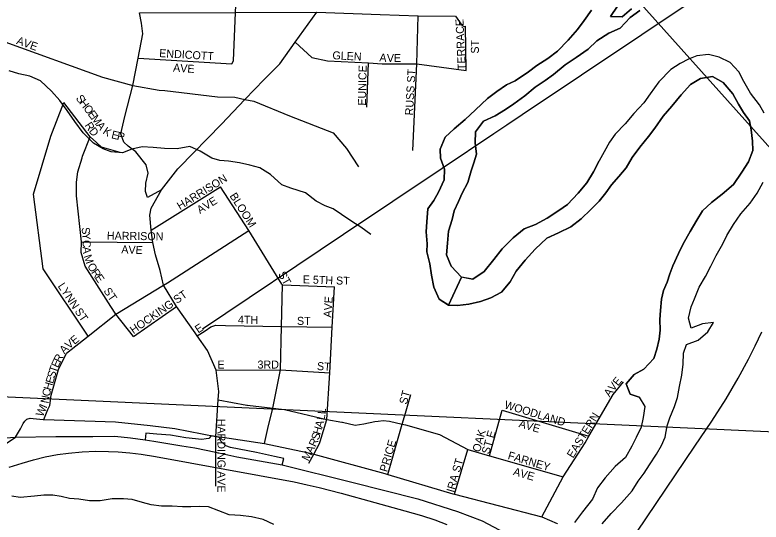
# Model space of a CAD drawing. Extents: x 1624196 to 2029251, y 146837 to 440034.
# Drawn here: x 1855581 to 1860244, y 275807 to 278973 of the extents above; entities that cross this region are included whole.
import ezdxf

# ---------------------------------------------------------------- set-up
doc = ezdxf.new("R2010")
doc.units = 0
for name, color, linetype in [('GM_P_State_Alignment', 7, 'Continuous'), ('GM_X_City_Street', 7, 'Continuous'), ('GM_X_City_Street_Text', 7, 'Continuous'), ('GM_X_Interchange_Ramps', 7, 'Continuous'), ('GM_X_Major_River', 7, 'Continuous'), ('GM_X_Minor_River', 7, 'Continuous'), ('GM_X_Rail_Line', 7, 'Continuous'), ('GM_X_Section', 7, 'Continuous'), ('GM_X_State_Route', 7, 'Continuous'), ('GM_X_US_Route', 7, 'Continuous')]:
    doc.layers.add(name, color=color, linetype=linetype)

msp = doc.modelspace()

# ---------------------------------------------------------------- linework, layer by layer
at = {"layer": 'GM_P_State_Alignment'}
msp.add_lwpolyline([(1861511.5, 276861.7), (1860431.7, 277996.1), (1859184.2, 279387.8), (1858872.6, 279744.1), (1858597.3, 280059.1), (1857442.1, 281556), (1857427.3, 281575.2), (1856929.1, 281940.1)], dxfattribs=at)
at = {"layer": 'GM_X_City_Street'}
for points in [[(1856947.1, 278686.4), (1856960, 278987.7), (1856972.7, 279283.3), (1856984.8, 279567.1)], [(1856496.6, 277882), (1856409.1, 277834), (1856397.6, 277871.4), (1856398.6, 277922.3), (1856413.5, 277986.2), (1856401.5, 278037.1), (1856335.8, 278117.6), (1856289.3, 278154.3), (1856261.8, 278178.9), (1856241.9, 278231.8), (1856267.8, 278338.6), (1856317.2, 278532.3), (1856350.2, 278702.4), (1856379.8, 278855.1), (1856372.2, 278921.9), (1856359.9, 278985.6)], [(1856359.9, 278985.6), (1856960, 278987.7), (1857468.3, 278989.5), (1857862.5, 278976.5), (1858101, 278967.5), (1858333, 278965.5), (1858374.4, 278910.1), (1858388.3, 278901.9), (1858396.4, 278903.8)], [(1858067.7, 278127), (1858093, 278667), (1858101, 278967.5)], [(1858401.6, 278626.9), (1858396.4, 278903.8)], [(1855518.1, 278804.9), (1856127.6, 278584.2), (1856317.2, 278532.3), (1856482.9, 278504.3), (1856517, 278500.3)], [(1857331.6, 278802.8), (1857436.4, 278707), (1857534.1, 278686), (1857789.6, 278674), (1857875.4, 278668), (1858093, 278667), (1858401.6, 278626.9)], [(1856350.2, 278702.4), (1856936.9, 278668.4), (1856947.1, 278686.4)], [(1857779.9, 278396.8), (1857789.6, 278674)], [(1856517, 278500.3), (1856846.6, 278461.4), (1856955.4, 278459.4), (1857018.2, 278445.4), (1857073.1, 278434.4), (1857296.6, 278343.6), (1857569.1, 278237.8), (1857653, 278139.3), (1857728, 278024.2)], [(1856038.1, 276968.4), (1855757.3, 277388.9), (1855696, 277855), (1855805.9, 278216.9), (1855886.2, 278426.7)], [(1856090.7, 278175.8), (1856090.1, 278176.2), (1856050.4, 278212.3), (1855886.2, 278426.7)], [(1856000.1, 278081), (1856002.9, 278090.8), (1856050.4, 278212.3)], [(1856237.4, 278114.8), (1856121.9, 278147.4), (1856090.7, 278175.8)], [(1856181, 277153.3), (1856019.3, 277404), (1855994.5, 277489.5), (1855996.9, 277556.3), (1855964.9, 277843.9), (1855964.9, 277928.6), (1855974.7, 277993.5), (1856000.1, 278081)], [(1856432, 277630.3), (1856866.1, 277900.3)], [(1857249.2, 277292.4), (1857042.4, 277628.1), (1856866.1, 277900.3)], [(1856533.3, 277300.8), (1857042.4, 277628.1)], [(1855996.9, 277556.3), (1856442.4, 277552.2)], [(1855760.6, 276447.4), (1855786.5, 276510.8), (1855799, 276535.7), (1855808, 276599.1), (1855854, 276759.4), (1855902.2, 276861.9), (1856038.1, 276968.4), (1856212.2, 277105), (1856509.9, 277285.7), (1856533.3, 277300.8)], [(1857161.9, 276391.5), (1857192.4, 276517.5), (1857240.7, 276757.7), (1857247.4, 277027.8), (1857251.8, 277288.3), (1857249.2, 277292.4)], [(1857251.8, 277288.3), (1857577.7, 277274.8)], [(1857487.7, 276310.6), (1857529, 276447.1), (1857548.3, 276738.4), (1857564.2, 277024), (1857577.7, 277274.8)], [(1856321.7, 276966), (1856212.2, 277105), (1856181, 277153.3)], [(1856321.7, 276966), (1856590.5, 277153.7)], [(1856719.8, 276969.3), (1856769.4, 277000.6), (1856804.9, 277025.4), (1856837, 277036.2), (1856897.3, 277035)], [(1856897.3, 277035), (1857247.4, 277027.8), (1857564.2, 277024)], [(1856837.6, 276755.8), (1857240.7, 276757.7), (1857548.3, 276738.4)], [(1858873.3, 275840.3), (1859006.8, 276089.1), (1859143.3, 276302.3), (1859167.5, 276344), (1859318.7, 276603.4), (1859383.6, 276682.9)], [(1858021, 276487.7), (1858021, 276487.7), (1858054.1, 276602.6)], [(1856850.1, 276569.6), (1857029.5, 276536.8), (1857033.2, 276536.3)], [(1857033.2, 276536.3), (1857192.4, 276517.5), (1857264.8, 276509.8), (1857529, 276447.1), (1857623.5, 276431.6), (1857627.9, 276430.6)], [(1857910.6, 276104.9), (1858001.2, 276419.1), (1858021, 276487.7)], [(1858546.2, 276220.8), (1858626.3, 276506.3)], [(1858626.3, 276506.3), (1859167.5, 276344)], [(1857627.9, 276430.6), (1857706, 276412.3), (1857761.9, 276420.1), (1857829.4, 276435.5), (1857850.6, 276437.4), (1857881.5, 276441.3), (1857922, 276437.4), (1858001.2, 276419.1), (1858022.3, 276414.3), (1858234.5, 276354.5), (1858411.1, 276259.4), (1858546.2, 276220.8), (1859006.8, 276089.1)], [(1857139.3, 276298.4), (1857161.9, 276391.5)], [(1856836.2, 276134.6), (1856836.2, 276134.7), (1856836.3, 276242.6), (1856836.4, 276342.3)], [(1856836.4, 276342.3), (1856877.2, 276336.8), (1857139.3, 276298.4), (1857407.3, 276242.1), (1857448.5, 276231), (1857892.6, 276110.2), (1857910.6, 276104.9), (1858317.8, 275984), (1858327.1, 275981.6), (1858873.3, 275840.3), (1858970.2, 275797.4), (1858972.2, 275796.5)], [(1857418.3, 276174), (1857448.5, 276231), (1857483.7, 276297.5), (1857487.7, 276310.6)], [(1858327.1, 275981.6), (1858411.1, 276259.4)], [(1856835.7, 276030.8), (1856836.2, 276134.6)]]:
    msp.add_lwpolyline(points, dxfattribs=at)
at = {"layer": 'GM_X_Interchange_Ramps'}
for points in [[(1856836.4, 276342.3), (1856806.1, 276344.5), (1856791.7, 276327.8), (1856775, 276325.7), (1856747.8, 276323.6), (1856647.7, 276334), (1856553.7, 276348.7), (1856468.2, 276355.9), (1856399.1, 276363.1), (1856394.3, 276320.3)], [(1857251.5, 276165.4), (1857260.6, 276203.8), (1857203.1, 276217.1), (1857089.5, 276242.2), (1856928.7, 276273.2), (1856897.7, 276283.5), (1856866.7, 276311.6), (1856858.6, 276334.9), (1856836.4, 276342.3)]]:
    msp.add_lwpolyline(points, dxfattribs=at)
at = {"layer": 'GM_X_Major_River'}
for p, q in [((1858370.4, 277336.8), (1858290.1, 277161.8)), ((1858290.1, 277161.8), (1858370.4, 277336.8))]:
    msp.add_line(p, q, dxfattribs=at)
for points in [[(1859433.2, 279010.7), (1859375.4, 278960.5), (1859303.4, 278964.3), (1859347.2, 279028.5)], [(1859347.2, 279028.5), (1859303.4, 278964.3), (1859375.4, 278960.5), (1859433.2, 279010.7)], [(1859183.4, 279002.1), (1859137.5, 278937.9), (1859095.7, 278881.7), (1859037.9, 278815.5), (1858972, 278747.2), (1858910.2, 278701), (1858842.3, 278656.8), (1858790.4, 278618.6), (1858706.6, 278562.3), (1858652.7, 278536.2), (1858592.8, 278496), (1858532.9, 278451.8), (1858459.1, 278381.5), (1858395.3, 278321.3), (1858325.5, 278261), (1858269.6, 278210.8), (1858237.8, 278134.6), (1858239.9, 278078.5), (1858266.1, 278010.5), (1858262.2, 277944.4), (1858228.4, 277866.2), (1858198.6, 277814), (1858160.7, 277761.9), (1858154.9, 277681.8), (1858151, 277619.6), (1858157.2, 277543.5), (1858155.3, 277493.5), (1858173.5, 277419.4), (1858183.6, 277349.3), (1858197.8, 277273.2), (1858232, 277199.2), (1858290.1, 277161.8)], [(1859480.7, 276587.2), (1859424.7, 276605.1), (1859400.6, 276669.1), (1859450.4, 276729.3), (1859510.3, 276761.5), (1859574.1, 276827.8), (1859592, 276885.9), (1859605.9, 276948), (1859613.7, 277006.1), (1859611.6, 277072.2), (1859615.4, 277128.3), (1859621.3, 277198.5), (1859633.1, 277252.6), (1859657, 277304.7), (1859672.9, 277356.8), (1859692.8, 277406.9), (1859726.6, 277483.1), (1859756.4, 277543.3), (1859800.2, 277621.5), (1859842, 277691.7), (1859877.9, 277749.9), (1859933.7, 277802.1), (1859999.6, 277854.3), (1860071.4, 277914.6), (1860123.2, 277990.8), (1860165, 278055), (1860192.9, 278127.2), (1860190.7, 278185.2), (1860182.6, 278255.3), (1860170.5, 278311.4), (1860134.3, 278363.4), (1860102.2, 278415.4), (1860066.1, 278481.4), (1860006, 278551.4), (1859939.9, 278589.3), (1859864, 278577.1), (1859802.1, 278538.9), (1859744.3, 278474.6), (1859686.5, 278404.4), (1859630.7, 278340.2), (1859578.9, 278265.9), (1859541, 278213.8), (1859485.2, 278147.5), (1859437.3, 278083.3), (1859399.5, 278019.1), (1859353.7, 277965), (1859307.8, 277912.8), (1859273.9, 277862.6), (1859232.1, 277810.5), (1859180.2, 277758.3), (1859118.4, 277700), (1859054.5, 277649.8), (1858978.6, 277613.6), (1858904.8, 277579.3), (1858831, 277511.1), (1858769.1, 277442.8), (1858713.3, 277372.6), (1858675.5, 277306.4), (1858621.7, 277242.2), (1858553.8, 277208), (1858489.9, 277183.8), (1858417.9, 277167.6), (1858346, 277159.4), (1858294, 277159.3), (1858232, 277199.2), (1858197.8, 277273.2), (1858183.6, 277349.3), (1858173.5, 277419.4), (1858155.3, 277493.5), (1858157.2, 277543.5), (1858151, 277619.6), (1858154.9, 277681.8), (1858160.7, 277761.9), (1858198.6, 277814), (1858228.4, 277866.2), (1858262.2, 277944.4), (1858266.1, 278010.5), (1858239.9, 278078.5), (1858237.8, 278134.6), (1858269.6, 278210.8), (1858325.5, 278261), (1858395.3, 278321.3), (1858459.1, 278381.5), (1858532.9, 278451.8), (1858592.8, 278496), (1858652.7, 278536.2), (1858706.6, 278562.3), (1858790.4, 278618.6), (1858842.3, 278656.8), (1858910.2, 278701), (1858972, 278747.2), (1859037.9, 278815.5), (1859095.7, 278881.7), (1859137.5, 278937.9), (1859183.4, 279002.1)], [(1858370.4, 277336.8), (1858307.5, 277405.7), (1858277.3, 277475.7), (1858283.1, 277547.8), (1858291, 277624), (1858312.8, 277696.1), (1858326.6, 277750.3), (1858352.5, 277808.4), (1858376.4, 277860.5), (1858410.2, 277926.7), (1858432, 277998.9), (1858447.9, 278049), (1858465.8, 278103.1), (1858457.6, 278175.2), (1858459.5, 278243.3), (1858509.3, 278309.5), (1858581.2, 278343.7), (1858647, 278381.9), (1858698.9, 278418.1), (1858766.8, 278468.3), (1858832.6, 278522.6), (1858894.5, 278564.8), (1858946.4, 278601), (1859020.2, 278661.2), (1859088.1, 278707.5), (1859163.9, 278759.7), (1859217.8, 278811.9), (1859291.6, 278860.2), (1859363.5, 278890.4), (1859425.3, 278956.6), (1859485.2, 279000.8)], [(1859485.2, 279000.8), (1859425.3, 278956.6), (1859363.5, 278890.4), (1859291.6, 278860.2), (1859217.8, 278811.9), (1859163.9, 278759.7), (1859088.1, 278707.5), (1859020.2, 278661.2), (1858946.4, 278601), (1858894.5, 278564.8), (1858832.6, 278522.6), (1858766.8, 278468.3), (1858698.9, 278418.1), (1858647, 278381.9), (1858581.2, 278343.7), (1858509.3, 278309.5), (1858459.5, 278243.3), (1858457.6, 278175.2), (1858465.8, 278103.1), (1858447.9, 278049), (1858432, 277998.9), (1858410.2, 277926.7), (1858376.4, 277860.5), (1858352.5, 277808.4), (1858326.6, 277750.3), (1858312.8, 277696.1), (1858291, 277624), (1858283.1, 277547.8), (1858277.3, 277475.7), (1858307.5, 277405.7), (1858369.6, 277337.7), (1858441.6, 277323.9), (1858513.4, 277372.1), (1858573.2, 277446.4), (1858625, 277512.6), (1858694.9, 277580.9), (1858762.7, 277637.1), (1858834.6, 277665.3), (1858906.5, 277703.5), (1858980.3, 277751.8), (1859034.2, 277790), (1859100, 277860.2), (1859153.8, 277924.4), (1859195.7, 277994.6), (1859231.5, 278062.8)], [(1860262.3, 278359.7), (1860234.2, 278411.7), (1860178.1, 278485.7), (1860135.9, 278557.7), (1860103.8, 278617.7), (1860049.7, 278675.6), (1859981.6, 278709.5), (1859915.6, 278725.4), (1859841.7, 278717.2), (1859789.8, 278697.1), (1859737.8, 278670.9), (1859680, 278632.7), (1859604.2, 278556.4), (1859550.4, 278480.2), (1859510.5, 278424), (1859448.7, 278357.8), (1859394.9, 278293.5), (1859331.1, 278229.3), (1859297.2, 278179.2), (1859263.3, 278119), (1859231.5, 278062.8)], [(1858290.1, 277161.8), (1858346, 277159.4), (1858417.9, 277167.6), (1858489.9, 277183.8), (1858553.8, 277208), (1858621.7, 277242.2), (1858675.5, 277306.4), (1858713.3, 277372.6), (1858769.1, 277442.8), (1858831, 277511.1), (1858904.8, 277579.3), (1858978.6, 277613.6), (1859054.5, 277649.8), (1859118.4, 277700), (1859180.2, 277758.3), (1859232.1, 277810.5), (1859273.9, 277862.6), (1859307.8, 277912.8), (1859353.7, 277965), (1859399.5, 278019.1), (1859437.3, 278083.3), (1859485.2, 278147.5), (1859541, 278213.8), (1859578.9, 278265.9), (1859630.7, 278340.2), (1859686.5, 278404.4), (1859744.3, 278474.6), (1859802.1, 278538.9), (1859864, 278577.1), (1859939.9, 278589.3), (1860006, 278551.4), (1860066.1, 278481.4), (1860102.2, 278415.4), (1860134.3, 278363.4), (1860170.5, 278311.4), (1860182.6, 278255.3), (1860190.7, 278185.2), (1860192.9, 278127.2), (1860165, 278055), (1860123.2, 277990.8), (1860071.4, 277914.6), (1859999.6, 277854.3), (1859933.7, 277802.1), (1859877.9, 277749.9), (1859842, 277691.7), (1859800.2, 277621.5), (1859756.4, 277543.3), (1859726.6, 277483.1), (1859692.8, 277406.9), (1859672.9, 277356.8), (1859657, 277304.7), (1859633.1, 277252.6), (1859621.3, 277198.5), (1859615.4, 277128.3), (1859611.6, 277072.2), (1859613.7, 277006.1), (1859605.9, 276948), (1859592, 276885.9), (1859574.1, 276827.8), (1859510.3, 276761.5), (1859450.4, 276729.3), (1859400.6, 276669.1), (1859424.7, 276605.1), (1859480.7, 276587.2)], [(1859231.5, 278062.8), (1859195.7, 277994.6), (1859153.8, 277924.4), (1859100, 277860.2), (1859034.2, 277790), (1858980.3, 277751.8), (1858906.5, 277703.5), (1858834.6, 277665.3), (1858762.7, 277637.1), (1858694.9, 277580.9), (1858625, 277512.6), (1858573.2, 277446.4), (1858513.4, 277372.1), (1858441.6, 277323.9), (1858370.4, 277336.8)], [(1859250.7, 275795.5), (1859306.5, 275859.7), (1859370.3, 275928), (1859438.1, 276002.2), (1859475.9, 276062.4), (1859513.8, 276112.6), (1859545.7, 276164.7), (1859589.5, 276230.9), (1859621.4, 276285.1), (1859643.2, 276337.2), (1859657.1, 276407.4), (1859672.9, 276457.5), (1859702.8, 276529.6), (1859720.6, 276583.8), (1859734.5, 276653.9), (1859748.3, 276724), (1859756.1, 276792.2), (1859758, 276862.3), (1859777.8, 276916.4), (1859849.7, 276942.6), (1859911.6, 276994.8), (1859945.4, 277053), (1859877.5, 277044.8), (1859807.6, 277018.6), (1859789.5, 277080.7), (1859807.3, 277150.8), (1859827.2, 277200.9), (1859857, 277273.1), (1859896.8, 277339.3), (1859928.6, 277405.5), (1859962.5, 277471.6), (1860004.3, 277543.9), (1860030.2, 277596), (1860072, 277664.2), (1860117.8, 277730.4), (1860175.6, 277798.6), (1860219.5, 277860.8), (1860257.3, 277929)], [(1859480.7, 276587.2), (1859516.9, 276529.2), (1859507, 276459.1), (1859493.2, 276399), (1859463.3, 276334.8), (1859435.5, 276280.6), (1859395.6, 276210.5), (1859331.8, 276154.2), (1859270, 276084), (1859222.2, 276019.8), (1859190.3, 275949.6), (1859128.6, 275871.3), (1859076.7, 275805.1)], [(1857197.7, 275792.7), (1857131.7, 275822.6), (1857059.6, 275840.5), (1856989.7, 275848.3), (1856919.7, 275852.2), (1856855.7, 275878), (1856789.6, 275901.9), (1856733.7, 275903.8), (1856679.7, 275901.7), (1856627.7, 275901.5), (1856563.7, 275905.4), (1856495.8, 275907.2), (1856431.8, 275915.1), (1856377.8, 275929), (1856313.8, 275948.9), (1856259.8, 275952.8), (1856187.8, 275952.6), (1856113.9, 275940.4), (1856045.9, 275940.2), (1855979.9, 275950.1), (1855922, 275954), (1855870, 275965.9), (1855818, 275975.8), (1855762, 275975.6), (1855702, 275969.5), (1855614.1, 275961.3), (1855562.1, 275969.2)]]:
    msp.add_lwpolyline(points, dxfattribs=at)
at = {"layer": 'GM_X_Minor_River'}
msp.add_lwpolyline([(1857805.3, 277602.8), (1857743.2, 277648.8), (1857693.1, 277678.7), (1857621.1, 277726.6), (1857569, 277762.5), (1857519, 277780.4), (1857462.9, 277810.3), (1857396.9, 277862.2), (1857304.8, 277892.1), (1857248.8, 277912), (1857178.7, 277975.9), (1857110.6, 278017.8), (1857048.6, 278035.7), (1856984.6, 278049.6), (1856914.6, 278059.4), (1856860.7, 278065.3), (1856810.7, 278079.2), (1856738.6, 278123.1), (1856674.6, 278151), (1856594.6, 278136.8), (1856514.7, 278138.6), (1856444.7, 278146.5), (1856376.7, 278150.3), (1856310.8, 278134.1), (1856252.9, 278112), (1856182.9, 278117.8), (1856132.8, 278137.7), (1856070.8, 278171.6), (1856006.7, 278237.6), (1855954.5, 278307.5), (1855906.4, 278377.5), (1855860.3, 278439.5), (1855810.2, 278497.5), (1855740.1, 278561.4), (1855674, 278591.3), (1855606, 278605.2), (1855544, 278623.1)], dxfattribs=at)
at = {"layer": 'GM_X_Rail_Line'}
for points in [[(1861190.3, 279752.5), (1861042.6, 279708), (1860975.4, 279686.1), (1860887.1, 279656.4), (1860685.4, 279574.4), (1860439.3, 279471.2), (1860368.2, 279438.4), (1860307.2, 279406.3), (1860246.2, 279372), (1860189.2, 279332.9), (1860132.1, 279289.9), (1860066.5, 279239.1), (1859997.7, 279186.7), (1859944.6, 279150), (1859869.6, 279099.2), (1858750.4, 278349.7), (1858654.3, 278285.7), (1858573.8, 278230.2), (1858250.3, 278013.7), (1857633.4, 277601.8), (1856753.7, 277011.2)], [(1859406.4, 275654.3), (1859830.5, 276280.3), (1859936.8, 276436.6), (1860025.1, 276577.3), (1860100.1, 276704.7), (1860164.2, 276823.5), (1860205.6, 276906.3), (1860247.8, 276994.6)], [(1855543.7, 276149.8), (1855625.1, 276175.6), (1855697.7, 276196.5), (1855769.4, 276213.4), (1855846, 276228), (1855914.5, 276236.8), (1856000.7, 276245.7), (1856086.2, 276248.9), (1856165.1, 276248.1), (1856225.6, 276245.7), (1856298.9, 276239.2), (1856369.1, 276230.4), (1856459.3, 276216.7), (1857325, 276057.9), (1857408, 276040.2), (1857481.3, 276022.4), (1857618.4, 275987.8), (1857830.3, 275929.7), (1858016.5, 275878.1), (1858120.5, 275847.5), (1858204.3, 275820.9), (1858279.3, 275792.7)]]:
    msp.add_lwpolyline(points, dxfattribs=at)
at = {"layer": 'GM_X_Section'}
msp.add_lwpolyline([(1855574.9, 282007.2), (1856638.9, 282002.1), (1862193.5, 281747.1), (1861882.7, 276297.8), (1854942.8, 276613.9)], close=True, dxfattribs=at)
at = {"layer": 'GM_X_State_Route'}
for points in [[(1856606.7, 278021.4), (1856872, 278290.7), (1857018.2, 278445.4), (1857138.6, 278569.2), (1857236.8, 278668), (1857331.6, 278802.8), (1857468.3, 278989.5)], [(1856706.2, 276988.7), (1856590.5, 277153.7), (1856509.9, 277285.7), (1856489.1, 277377.7), (1856458.5, 277475), (1856442.4, 277552.2), (1856432, 277630.3), (1856424.7, 277724), (1856431.7, 277767.7), (1856496.6, 277882), (1856598.6, 278013.2), (1856606.7, 278021.4)], [(1856836.4, 276342.3), (1856850.1, 276569.6), (1856854.9, 276621.7), (1856837.6, 276755.8), (1856784.3, 276878), (1856719.8, 276969.3), (1856706.2, 276988.7)], [(1855480.6, 276268.9), (1855583.9, 276336.2), (1855614.7, 276389.8), (1855632.7, 276422.6), (1855641.8, 276436.1), (1855654.2, 276448.6), (1855675.7, 276455.4), (1855693.8, 276453.1), (1855758.2, 276447.6)], [(1855758.2, 276447.6), (1855760.6, 276447.4), (1856208.4, 276433.1), (1856425.6, 276410.1), (1856580.1, 276391.3), (1856836.4, 276342.3)]]:
    msp.add_lwpolyline(points, dxfattribs=at)
at = {"layer": 'GM_X_US_Route'}
for points in [[(1855060.6, 276249.1), (1855211, 276291.8), (1855365.5, 276323.1), (1855583.9, 276336.2), (1855836.5, 276341.5), (1856067.3, 276341.5), (1856205.3, 276343.3), (1856302.3, 276333.2), (1856394.3, 276320.3), (1856448, 276311.8)], [(1856448, 276311.8), (1856623.1, 276283.9), (1856705.2, 276269.9), (1856836.3, 276242.6), (1856967.1, 276215.4), (1857251.5, 276165.4), (1857686.4, 276057.2), (1858097.6, 275952.9), (1858346.4, 275873.8), (1858501.3, 275814.4), (1858778.9, 275668.1), (1858893.8, 275595.1), (1859102.5, 275452.4), (1859372.9, 275239.2), (1859611.8, 275025), (1859838.3, 274820.7), (1860231.5, 274460.5), (1860518.4, 274177.2)]]:
    msp.add_lwpolyline(points, dxfattribs=at)

# ---------------------------------------------------------------- texts
at = {"layer": 'GM_X_City_Street_Text'}
for s, rotation, p in [('TERRACE', 92.7687, (1858398.6, 278630)), ('AVE', 340.3457, (1855586.4, 278793.3)), ('ST', 90, (1858480.2, 278731.6)), ('ENDICOTT', 356.6825, (1856481.3, 278710.2)), ('GLEN', 356.9079, (1857563.7, 278697)), ('A', 355.2854, (1857856.9, 278683.4)), ('V', 359.7337, (1857905, 278679.6)), ('E', 359.9956, (1857949.3, 278679.4)), ('AVE', 356.0531, (1856567.9, 278620)), ('EUNICE', 88.8773, (1857773.8, 278406.2)), ('RUSS ST', 86.8178, (1858068.6, 278344.9)), ('S', 307.0639, (1855958.6, 278452)), ('H', 307.0744, (1855979.9, 278423.9)), ('O', 307.0744, (1856006.4, 278388.8)), ('E', 307.0748, (1856032.9, 278353.7)), ('M', 307.0736, (1856054.1, 278325.6)), ('R', 302.9424, (1856014.7, 278284.2)), ('A', 307.0744, (1856086, 278283.5)), ('D', 309.2211, (1856039.6, 278246.2)), ('K', 326.4343, (1856125.8, 278235.8)), ('E', 346.5679, (1856180, 278203.9)), ('R', 347.7609, (1856215.4, 278195.4)), ('HARRISON', 31.6609, (1856612.2, 277754)), ('BLOOM', 302.7358, (1856919.9, 277843.5)), ('AVE', 32.0021, (1856737, 277729.5)), ('S', 275.1153, (1855997.3, 277645.9)), ('Y', 275.1373, (1856000.5, 277610.8)), ('HARRISON', 359.1935, (1856155.3, 277570.6)), ('C', 269.83, (1856004.4, 277568.2)), ('AVE', 358.0264, (1856244.9, 277484.6)), ('A', 273.2922, (1856004.3, 277525.3)), ('M', 288.3213, (1856009.5, 277467.3)), ('O', 300.4857, (1856030.9, 277406.7)), ('R', 304.2219, (1856055.2, 277365.8)), ('E', 304.1145, (1856077.4, 277333)), ('ST', 299.7432, (1857223.7, 277354.7)), ('E 5TH ST', 357.9897, (1857378.7, 277297.8)), ('LYNN', 303.6885, (1855846.2, 277280.4)), ('ST', 304.7022, (1856132.1, 277249.8)), ('HOCKING ST', 34.8246, (1856321.4, 276979.3)), ('AVE', 86.0569, (1857558.2, 277082.3)), ('ST', 304.7061, (1855951.7, 277122.2)), ('4TH', 358.3643, (1856973.8, 277047)), ('ST', 0, (1857343.2, 277038.2)), ('E', 33.6859, (1856726.4, 276983.8)), ('E', 38.9905, (1855952.3, 276912.5)), ('V', 39.4978, (1855918.5, 276884.6)), ('A', 46.4605, (1855889.3, 276853.8)), ('R', 63.4947, (1855864.5, 276798.3)), ('T', 70.8479, (1855838.7, 276734.7)), ('E', 65.0417, (1855849.8, 276766.7)), ('E', 0, (1856846, 276765.4)), ('3RD', 0, (1857096.8, 276765.4)), ('ST', 356.4262, (1857467, 276756.6)), ('S', 73.3191, (1855828.8, 276701.5)), ('E', 73.3191, (1855818.7, 276667.8)), ('E', 50.2137, (1859349.3, 276653.4)), ('H', 73.7634, (1855806.4, 276625.7)), ('V', 50.7975, (1859321.6, 276619.4)), ('C', 76.3701, (1855797.2, 276587.8)), ('ST', 75.064, (1858029.3, 276538.4)), ('A', 55.0671, (1859297, 276584.1)), ('N', 79.5793, (1855789.4, 276545.2)), ('WOODLAND', 343.1017, (1858635.1, 276518.6)), ('W', 67.0277, (1855755.1, 276460.8)), ('I', 67.0052, (1855777.4, 276513.5)), ('L', 84.6762, (1857521.3, 276478.9)), ('L', 80.6449, (1857515.1, 276440.3)), ('EASTERN', 58.2757, (1859068.8, 276202.3)), ('HARDING AVE', 270, (1856846.6, 276452.4)), ('A', 73.9602, (1857501.5, 276391.8)), ('AVE', 344.0556, (1858725.7, 276400.8)), ('H', 73.7745, (1857489.2, 276349.4)), ('OAK', 74.5786, (1858486.5, 276240.2)), ('ST E', 73.497, (1858543.6, 276227.6)), ('R', 65.5489, (1857459.6, 276272.4)), ('S', 72.6909, (1857478.4, 276314.8)), ('PRICE', 73.4401, (1857906.2, 276116.3)), ('A', 62.7172, (1857438.2, 276230.9)), ('M', 62.7182, (1857414, 276184)), ('FARNEY', 343.4952, (1858657.1, 276201.8)), ('IRA ST', 74.058, (1858324.1, 275988.6)), ('AVE', 344.052, (1858690.5, 276101.6))]:
    msp.add_text(s, height=50, rotation=rotation, dxfattribs=at).set_placement(p)

doc.saveas('drawing.dxf')
